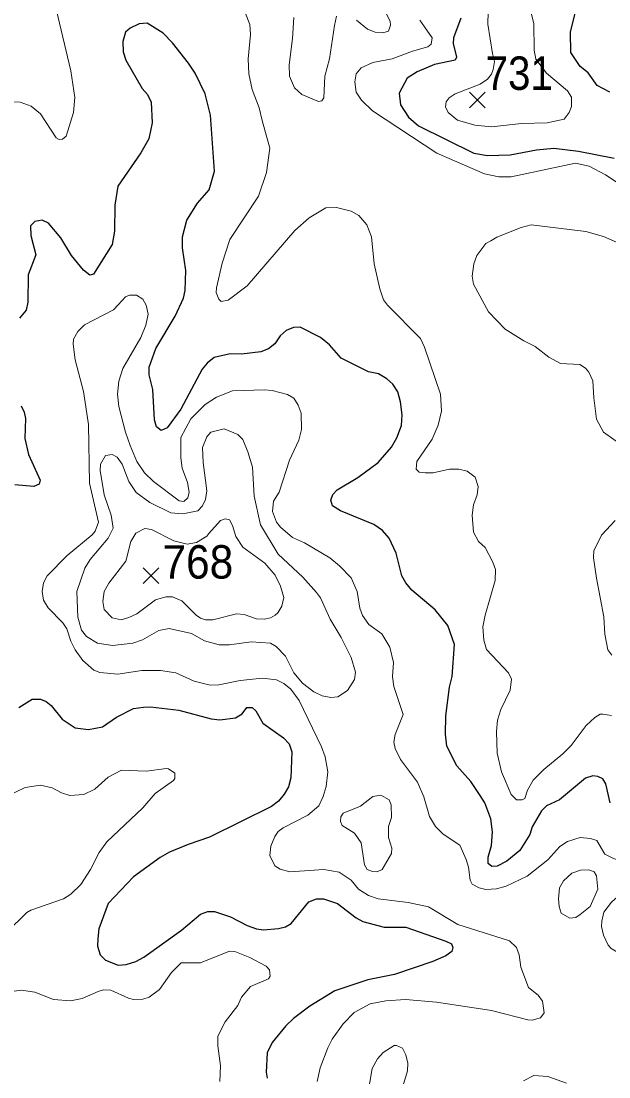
# Model space of a CAD drawing. Extents: x 294.2 to 320.3, y 7482.7 to 7510.7.
# Drawn here: x 317.439 to 318.846, y 7505.662 to 7508.188 of the extents above; entities that cross this region are included whole.
import ezdxf
from ezdxf.enums import TextEntityAlignment as Align

# ---------------------------------------------------------------- set-up
doc = ezdxf.new("R2010")
doc.units = 0
doc.header["$LTSCALE"] = 0.032
for name, color, linetype, lineweight in [('1', 7, 'Continuous', 25), ('2', 7, 'Continuous', 13), ('21', 7, 'Continuous', 25)]:
    doc.layers.add(name, color=color, linetype=linetype, lineweight=lineweight)
doc.layers.add('61', color=7, linetype='Continuous')

msp = doc.modelspace()

# ---------------------------------------------------------------- linework, layer by layer
at = {"layer": '1'}
for points in [[(318.8488, 7508.0179), (318.8183, 7508.034), (318.7967, 7508.0641), (318.7778, 7508.0797), (318.7551, 7508.1125), (318.7546, 7508.1614), (318.7662, 7508.2098)], [(318.4919, 7508.1953), (318.4742, 7508.148), (318.4737, 7508.134), (318.482, 7508.1017), (318.4787, 7508.0942), (318.4293, 7508.084), (318.3875, 7508.0667), (318.3638, 7508.0514), (318.3447, 7508.0156), (318.3472, 7507.9875), (318.3664, 7507.9581), (318.3906, 7507.937), (318.5228, 7507.8719), (318.556, 7507.8662), (318.6103, 7507.8676), (318.6729, 7507.8799), (318.7145, 7507.8843), (318.7733, 7507.8768), (318.8587, 7507.8601)], [(318.0595, 7507.4345), (318.0467, 7507.4156), (318.0312, 7507.4038), (318.0129, 7507.3962), (317.9668, 7507.3909), (317.9402, 7507.3914), (317.9019, 7507.3828), (317.8847, 7507.3693), (317.8731, 7507.3554), (317.8215, 7507.2591), (317.7887, 7507.215), (317.7749, 7507.2085), (317.7632, 7507.2171), (317.7588, 7507.2338), (317.7544, 7507.3064), (317.7461, 7507.3414), (317.7461, 7507.3602), (317.7622, 7507.4043), (317.8082, 7507.4817), (317.8282, 7507.5253), (317.832, 7507.543), (317.8337, 7507.5909), (317.826, 7507.6452), (317.826, 7507.6716), (317.8359, 7507.7119), (317.862, 7507.7522), (317.8897, 7507.7845), (317.9024, 7507.8286), (317.893, 7507.963), (317.8802, 7508.0141), (317.8558, 7508.0636), (317.8398, 7508.0873), (317.802, 7508.1362), (317.7793, 7508.1588), (317.741, 7508.183), (317.7216, 7508.1814), (317.7005, 7508.1712), (317.6889, 7508.1615), (317.6828, 7508.1394), (317.6833, 7508.1141), (317.69, 7508.0948), (317.7294, 7508.027), (317.7416, 7508.0125), (317.7504, 7507.9937), (317.7527, 7507.9448), (317.7449, 7507.9066), (317.7256, 7507.8727), (317.6712, 7507.7931), (317.6634, 7507.7474), (317.6629, 7507.6855), (317.6573, 7507.6532), (317.6129, 7507.5823), (317.604, 7507.5801), (317.5891, 7507.592), (317.5602, 7507.6269), (317.5341, 7507.6694), (317.5047, 7507.7044), (317.4898, 7507.7114), (317.4726, 7507.7087), (317.462, 7507.6979), (317.4626, 7507.6748), (317.4748, 7507.6286), (317.4559, 7507.5807), (317.4553, 7507.5157), (317.4514, 7507.4963), (317.4359, 7507.4775)], [(318.2059, 7507.3812), (318.1776, 7507.4135), (318.156, 7507.4312), (318.1077, 7507.4554), (318.0917, 7507.4549), (318.0739, 7507.4474), (318.0595, 7507.4345)], [(318.8498, 7506.3175), (318.8393, 7506.3632), (318.8321, 7506.3745), (318.8199, 7506.3804), (318.8077, 7506.382), (318.7905, 7506.3761), (318.7278, 7506.3245), (318.6967, 7506.31), (318.6851, 7506.2982), (318.6629, 7506.26), (318.6574, 7506.2417), (318.6329, 7506.2035), (318.6018, 7506.1777), (318.5786, 7506.1659), (318.5658, 7506.1648), (318.5575, 7506.1723), (318.5575, 7506.1874), (318.5652, 7506.2153), (318.568, 7506.2476), (318.5636, 7506.2788), (318.5491, 7506.317), (318.5386, 7506.3347), (318.5159, 7506.368), (318.4821, 7506.4062), (318.4588, 7506.453), (318.4549, 7506.482), (318.456, 7506.5256), (318.4649, 7506.5944), (318.471, 7506.6197), (318.4771, 7506.6961), (318.4605, 7506.7417), (318.4305, 7506.7788), (318.3745, 7506.8261), (318.3606, 7506.8434), (318.3506, 7506.8606), (318.3368, 7506.9144), (318.3201, 7506.9509), (318.3046, 7506.9687), (318.2841, 7506.9832), (318.2037, 7507.016), (318.1848, 7507.0284), (318.1804, 7507.0413), (318.1859, 7507.0553), (318.1959, 7507.066), (318.2458, 7507.0957), (318.2941, 7507.1317), (318.3257, 7507.1688), (318.3385, 7507.1909), (318.3501, 7507.2204), (318.3518, 7507.2457), (318.3479, 7507.2769), (318.3412, 7507.3011), (318.329, 7507.3189), (318.3152, 7507.3323), (318.2952, 7507.3436), (318.2708, 7507.3484), (318.2059, 7507.3812)], [(317.4393, 7507.2673), (317.447, 7507.252), (317.4502, 7507.2367), (317.4479, 7507.1893), (317.4567, 7507.1511), (317.485, 7507.0893), (317.4828, 7507.0796), (317.47, 7507.0742), (317.4245, 7507.0785)], [(317.4343, 7506.5452), (317.4659, 7506.5657), (317.4859, 7506.5657), (317.4997, 7506.5598), (317.5114, 7506.5506), (317.538, 7506.5178), (317.5685, 7506.4968), (317.6007, 7506.4925), (317.6345, 7506.4995), (317.6678, 7506.5221), (317.7083, 7506.5431), (317.7327, 7506.5464), (317.7488, 7506.5474), (317.817, 7506.5388), (317.894, 7506.5184), (317.9151, 7506.5162), (317.9528, 7506.5205), (317.9689, 7506.5302), (317.98, 7506.5453), (317.9927, 7506.5453), (318.0011, 7506.5377), (318.0182, 7506.5081), (318.0671, 7506.4732), (318.081, 7506.4587), (318.0876, 7506.4394), (318.0854, 7506.3775), (318.0798, 7506.356), (318.0687, 7506.3383), (318.0554, 7506.3216), (318.0388, 7506.3082), (317.8907, 7506.235), (317.8391, 7506.2178), (317.7947, 7506.199), (317.7726, 7506.1867)], [(317.7726, 7506.1867), (317.7082, 7506.1404), (317.6478, 7506.0765), (317.6256, 7506.0157), (317.6228, 7505.9926), (317.6222, 7505.9743), (317.6289, 7505.9538)], [(317.6289, 7505.9538), (317.6411, 7505.9409), (317.6716, 7505.9291), (317.691, 7505.9308), (317.7137, 7505.9377), (317.7332, 7505.948), (317.823, 7506.0125), (317.8684, 7506.0507), (317.8862, 7506.0572), (317.9022, 7506.0572), (317.9405, 7506.0448), (317.9804, 7506.0239), (318.0032, 7506.0158), (318.0198, 7506.0131), (318.0558, 7506.0163), (318.0719, 7506.0206), (318.0858, 7506.0287), (318.1279, 7506.0808), (318.1462, 7506.0873), (318.1634, 7506.0878), (318.1967, 7506.0765), (318.2416, 7506.042), (318.2577, 7506.0334), (318.3083, 7506.0197), (318.3607, 7506.0197), (318.4558, 7505.9865), (318.4697, 7505.9801), (318.473, 7505.9715), (318.4708, 7505.9618), (318.4564, 7505.9516), (318.4248, 7505.9376), (318.3333, 7505.9064), (318.269, 7505.894), (318.1902, 7505.8671), (318.1303, 7505.8306), (318.0915, 7505.801), (318.0732, 7505.7838), (318.0405, 7505.7435), (318.0283, 7505.7193), (318.0261, 7505.6725), (318.0283, 7505.6585)]]:
    msp.add_lwpolyline(points, dxfattribs=at)
at = {"layer": '2'}
for points in [[(318.5797, 7506.5152), (318.5879, 7506.5407), (318.6103, 7506.5867), (318.6129, 7506.6135), (318.6058, 7506.6288), (318.5536, 7506.6845), (318.5467, 7506.7062), (318.545, 7506.7385), (318.5501, 7506.7661), (318.5742, 7506.849), (318.5748, 7506.8754), (318.5685, 7506.8933), (318.5501, 7506.9283), (318.534, 7506.9428), (318.5225, 7506.9648), (318.5191, 7507.006), (318.5219, 7507.0305), (318.5311, 7507.0542), (318.5334, 7507.0742), (318.5259, 7507.097), (318.507, 7507.1109), (318.4875, 7507.1159), (318.4651, 7507.1159), (318.4258, 7507.107), (318.4066, 7507.107), (318.3919, 7507.1089), (318.3849, 7507.116), (318.3868, 7507.1345), (318.4232, 7507.1875), (318.4379, 7507.2207), (318.4456, 7507.2545), (318.4436, 7507.2954), (318.4047, 7507.4078), (318.3951, 7507.4282), (318.3164, 7507.5081), (318.3072, 7507.5209), (318.298, 7507.5476), (318.2843, 7507.6075), (318.2779, 7507.6715), (318.2671, 7507.7002), (318.2475, 7507.7225), (318.2292, 7507.733), (318.1947, 7507.7419), (318.1689, 7507.7408), (318.1293, 7507.7171), (318.0943, 7507.6865), (317.9801, 7507.5548), (317.9347, 7507.52), (317.9181, 7507.5167), (317.9124, 7507.5222), (317.906, 7507.5389), (317.9072, 7507.5501), (317.9204, 7507.6091), (317.9387, 7507.6656), (318.0076, 7507.7692), (318.0267, 7507.8253), (318.035, 7507.8841), (318.0165, 7507.9498), (318.0089, 7507.9805), (317.9923, 7508.0245), (317.9846, 7508.0616), (317.9826, 7508.0973), (317.9884, 7508.1561), (317.9865, 7508.1797), (317.9642, 7508.2365)], [(318.5585, 7508.2404), (318.5567, 7508.1803), (318.5681, 7508.1101), (318.5727, 7508.0912), (318.5693, 7508.0723), (318.5654, 7508.0613), (318.556, 7508.0494), (318.5382, 7508.0373), (318.4781, 7508.0143), (318.4641, 7508.0047), (318.457, 7507.9951), (318.4551, 7507.983), (318.4615, 7507.9696), (318.4839, 7507.9511), (318.5254, 7507.9389), (318.565, 7507.9351), (318.6373, 7507.943), (318.699, 7507.9447), (318.7393, 7507.9536), (318.7514, 7507.969), (318.7572, 7507.9837), (318.7565, 7508.006), (318.7476, 7508.0213), (318.6971, 7508.0634), (318.6719, 7508.0972), (318.6677, 7508.1184), (318.6669, 7508.1821), (318.6607, 7508.2073)], [(317.5204, 7508.2301), (317.5587, 7508.0692), (317.5676, 7508.0054), (317.5645, 7507.9696), (317.5472, 7507.9128), (317.5383, 7507.9051), (317.5306, 7507.9045), (317.5236, 7507.9083), (317.4859, 7507.9664), (317.4636, 7507.9843), (317.4374, 7507.9939), (317.4144, 7507.9951), (317.3966, 7507.9939), (317.3736, 7507.9869)], [(318.3028, 7508.2262), (318.3229, 7508.1878), (318.324, 7508.1783), (318.3188, 7508.1639), (318.3051, 7508.16), (318.2873, 7508.1616), (318.2683, 7508.1689), (318.2419, 7508.19)], [(318.194, 7508.2001), (318.1895, 7508.1778), (318.1774, 7508.0973), (318.1665, 7508.0565), (318.164, 7508.0041), (318.1589, 7507.9971), (318.1512, 7507.9958), (318.1114, 7508.0125), (318.0942, 7508.0281), (318.0821, 7508.0559), (318.081, 7508.0832), (318.0893, 7508.1465), (318.0919, 7508.1969)], [(318.3938, 7508.1905), (318.4053, 7508.1739), (318.4232, 7508.1478), (318.4213, 7508.1331), (318.413, 7508.1261), (318.376, 7508.1158), (318.3275, 7508.0973), (318.2815, 7508.089), (318.2537, 7508.076), (318.2411, 7508.0621), (318.2382, 7508.0426), (318.2416, 7508.0181), (318.2543, 7507.9986), (318.2802, 7507.9734), (318.4347, 7507.8719), (318.5484, 7507.8221), (318.5829, 7507.8151), (318.6122, 7507.8151), (318.7667, 7507.8482), (318.7989, 7507.841), (318.8385, 7507.8199), (318.911, 7507.7723)], [(318.8331, 7507.6727), (318.791, 7507.6842), (318.6607, 7507.7008), (318.6365, 7507.6944), (318.5784, 7507.6708), (318.5637, 7507.6619), (318.5522, 7507.6555)], [(318.5522, 7507.6555), (318.5305, 7507.6274), (318.5228, 7507.607), (318.519, 7507.5776), (318.5222, 7507.5585), (318.5579, 7507.4921), (318.5982, 7507.4505), (318.6429, 7507.4225), (318.6697, 7507.4097), (318.7029, 7507.3835), (318.7303, 7507.3688), (318.777, 7507.3663), (318.7903, 7507.3573), (318.7986, 7507.3477), (318.8082, 7507.3273), (318.8101, 7507.2865), (318.817, 7507.2356), (318.8331, 7507.2044), (318.8829, 7507.1689)], [(318.9225, 7507.6332), (318.8331, 7507.6727)], [(318.8369, 7506.1946), (318.8172, 7506.2272), (318.8025, 7506.2323), (318.7776, 7506.2342), (318.7476, 7506.2247), (318.7291, 7506.2132), (318.7003, 7506.1812), (318.6505, 7506.1417), (318.6007, 7506.118), (318.5777, 7506.1116), (318.5522, 7506.1097), (318.5356, 7506.1136), (318.519, 7506.1225), (318.5145, 7506.1321), (318.5107, 7506.1633), (318.5049, 7506.1819), (318.4896, 7506.2157), (318.4494, 7506.2425), (318.4315, 7506.2604), (318.4168, 7506.2847), (318.4034, 7506.3313), (318.3881, 7506.3671), (318.3479, 7506.4207), (318.3351, 7506.4475), (318.3319, 7506.4628), (318.3351, 7506.4807), (318.3536, 7506.5286), (318.3312, 7506.5956), (318.3287, 7506.6186), (318.3306, 7506.6531), (318.3223, 7506.6901), (318.3025, 7506.7214), (318.2719, 7506.7437), (318.2566, 7506.7655), (318.2502, 7506.7833), (318.2438, 7506.8229), (318.2291, 7506.8561), (318.2017, 7506.8848), (318.1787, 7506.9033), (318.1174, 7506.9398), (318.0893, 7506.9525), (318.0606, 7506.9768), (318.051, 7506.989), (318.0412, 7507.0146), (318.0435, 7507.0391), (318.0573, 7507.0608), (318.0816, 7507.1371), (318.104, 7507.1855), (318.1103, 7507.2111), (318.1097, 7507.2494), (318.1027, 7507.2692), (318.0923, 7507.286), (318.0768, 7507.2944), (318.0406, 7507.3039), (318.0223, 7507.3056), (317.9457, 7507.303), (317.9073, 7507.2884), (317.8799, 7507.2705), (317.8454, 7507.2366), (317.8217, 7507.1919), (317.8217, 7507.143), (317.8252, 7507.1185), (317.8377, 7507.084), (317.8416, 7507.0604), (317.8382, 7507.0468), (317.8288, 7507.0387), (317.818, 7507.04), (317.756, 7507.086), (317.7349, 7507.107), (317.7164, 7507.1345), (317.7004, 7507.1728), (317.6889, 7507.2047), (317.6736, 7507.266), (317.6705, 7507.2954), (317.673, 7507.3261), (317.6826, 7507.3567), (317.726, 7507.4308), (317.7381, 7507.4601), (317.7433, 7507.4869), (317.7387, 7507.5086), (317.7305, 7507.5227), (317.7158, 7507.5323), (317.6992, 7507.5323), (317.6896, 7507.5284), (317.6717, 7507.5087), (317.6602, 7507.4971), (317.5913, 7507.4614), (317.5753, 7507.4454), (317.5651, 7507.4269), (317.5638, 7507.4148), (317.5689, 7507.3771), (317.5887, 7507.3018), (317.6008, 7507.2226), (317.6034, 7507.0822), (317.6248, 7506.9889)], [(317.6248, 7506.9889), (317.6168, 7506.9678), (317.6093, 7506.9589), (317.5497, 7506.9095), (317.5014, 7506.8603), (317.4927, 7506.8441), (317.4898, 7506.8229)], [(318.8612, 7506.9927), (318.8293, 7506.9589), (318.8101, 7506.9212), (318.8095, 7506.9034), (318.8165, 7506.8549), (318.8344, 7506.7623), (318.8363, 7506.7208), (318.844, 7506.6831), (318.8535, 7506.6709)], [(317.4898, 7506.8229), (317.493, 7506.8025), (317.5038, 7506.784), (317.5396, 7506.7482), (317.5485, 7506.7335), (317.5581, 7506.7042), (317.5689, 7506.6837), (317.5874, 7506.6582), (317.6136, 7506.6352), (317.6277, 7506.6295), (317.6711, 7506.6256), (317.7286, 7506.6339), (317.7733, 7506.6339), (317.8096, 7506.6282), (317.8537, 7506.6084), (317.892, 7506.5988), (317.9125, 7506.5994), (317.9635, 7506.6103), (318.0172, 7506.616), (318.0504, 7506.6116), (318.0682, 7506.6027), (318.0848, 7506.5892), (318.1046, 7506.5624), (318.1583, 7506.4513), (318.1672, 7506.4271), (318.1736, 7506.3913), (318.1698, 7506.3568), (318.1627, 7506.3326), (318.1519, 7506.3102), (318.1257, 7506.2879), (318.067, 7506.2579), (318.0548, 7506.2489), (318.0465, 7506.2368), (318.0369, 7506.2138), (318.0344, 7506.1915), (318.0471, 7506.1666), (318.0593, 7506.1583), (318.0823, 7506.1519), (318.164, 7506.1576), (318.201, 7506.1512), (318.2291, 7506.1321), (318.247, 7506.1104), (318.2713, 7506.0957), (318.2943, 7506.088), (318.3658, 7506.0791), (318.4143, 7506.0682), (318.4851, 7506.0261), (318.6084, 7505.9872), (318.6256, 7505.9712), (318.632, 7505.9533), (318.6358, 7505.924), (318.6543, 7505.8754), (318.6769, 7505.8574), (318.6872, 7505.8424), (318.6912, 7505.8145), (318.6825, 7505.8026), (318.663, 7505.7976), (318.6527, 7505.7981), (318.565, 7505.8205), (318.4335, 7505.8403), (318.3594, 7505.8467), (318.3121, 7505.8435), (318.2751, 7505.8365), (318.2368, 7505.8154), (318.2106, 7505.7886), (318.1838, 7505.7515), (318.1736, 7505.7311), (318.155, 7505.6832), (318.148, 7505.6507)], [(318.8529, 7506.526), (318.8317, 7506.5299), (318.8254, 7506.5294), (318.8127, 7506.5216), (318.7921, 7506.5027), (318.7559, 7506.4545), (318.7361, 7506.4347), (318.6907, 7506.3971), (318.6652, 7506.3715), (318.6518, 7506.3479), (318.6448, 7506.3281), (318.639, 7506.3249)], [(318.639, 7506.3249), (318.6256, 7506.3243), (318.6122, 7506.337), (318.5892, 7506.3913), (318.579, 7506.436), (318.5771, 7506.4884), (318.5797, 7506.5152)], [(317.3806, 7506.3217), (317.4489, 7506.3543), (317.486, 7506.3594), (317.514, 7506.3536), (317.5364, 7506.3409), (317.5562, 7506.3351), (317.5894, 7506.337), (317.6155, 7506.3498), (317.6481, 7506.3785), (317.68, 7506.3958), (317.7388, 7506.3932), (317.7873, 7506.3996), (317.7924, 7506.399), (317.8071, 7506.3881), (317.8077, 7506.3753), (317.8039, 7506.3709), (317.7605, 7506.3396), (317.7311, 7506.3057), (317.6449, 7506.224), (317.6264, 7506.1985), (317.6053, 7506.1576), (317.5824, 7506.1219), (317.5587, 7506.0989), (317.5409, 7506.088), (317.463, 7506.0606), (317.4534, 7506.0548), (317.4049, 7506.0082)], [(318.897, 7506.1199), (318.9033, 7506.1334), (318.9053, 7506.1513), (318.904, 7506.1615), (318.897, 7506.171), (318.8574, 7506.1838), (318.8369, 7506.1946)], [(319.2364, 7505.6612), (319.2065, 7505.6717), (319.1473, 7505.6749), (319.1294, 7505.68), (319.1191, 7505.6877), (319.1115, 7505.7062), (319.0981, 7505.7222), (319.0176, 7505.7566), (318.9959, 7505.7727), (318.9758, 7505.8105), (318.9653, 7505.8499), (318.948, 7505.8908), (318.9314, 7505.9144), (318.9078, 7505.9361), (318.8516, 7505.9686), (318.8446, 7505.9769), (318.8331, 7506.0006), (318.8287, 7506.0216), (318.8299, 7506.0338), (318.8344, 7506.0554), (318.8523, 7506.0797), (318.897, 7506.1199)], [(317.3812, 7505.8614), (317.44, 7505.869), (317.4719, 7505.8645), (317.5166, 7505.8467), (317.5575, 7505.8435), (317.5856, 7505.8492), (317.6239, 7505.8658), (317.6366, 7505.8697), (317.6538, 7505.869), (317.6966, 7505.8499), (317.7081, 7505.8467), (317.7311, 7505.8473), (317.7458, 7505.8524), (317.7707, 7505.8703), (317.7994, 7505.9112), (317.8224, 7505.9341), (317.869, 7505.9341), (317.938, 7505.9622)], [(317.938, 7505.9622), (317.9508, 7505.9616), (317.9865, 7505.9476), (318.0261, 7505.9265), (318.0337, 7505.9175), (318.0357, 7505.9028), (318.0312, 7505.8965)], [(318.0312, 7505.8965), (317.9884, 7505.878), (317.9673, 7505.8524), (317.9578, 7505.832), (317.9277, 7505.7931), (317.9099, 7505.7592), (317.9099, 7505.7362), (317.9163, 7505.6877), (317.915, 7505.6507)], [(318.6422, 7505.652), (318.6671, 7505.6647), (318.7003, 7505.6628), (318.745, 7505.6462)]]:
    msp.add_lwpolyline(points, dxfattribs=at)
for points in [[(318.2208, 7506.5864), (318.1978, 7506.5713), (318.1806, 7506.5694), (318.1602, 7506.5733), (318.1404, 7506.5828), (318.1129, 7506.6039), (318.0925, 7506.6288), (318.072, 7506.6684), (318.0497, 7506.6914), (318.0363, 7506.6997), (317.9903, 7506.7029), (317.938, 7506.6952), (317.9137, 7506.6952), (317.8786, 7506.7048), (317.8473, 7506.7227), (317.7937, 7506.7348), (317.7694, 7506.7297), (317.7299, 7506.7074), (317.7069, 7506.6997), (317.6583, 7506.6939), (317.6226, 7506.6997), (317.5958, 7506.7156), (317.5836, 7506.7303), (317.5753, 7506.7616), (317.5727, 7506.8229), (317.5919, 7506.8791), (317.6047, 7506.8995), (317.6476, 7506.9503), (317.6594, 7506.9747), (317.6547, 7507.0061), (317.6385, 7507.0547), (317.6283, 7507.1128), (317.6296, 7507.1281), (317.6417, 7507.1485), (317.6571, 7507.1505), (317.6692, 7507.1447), (317.6813, 7507.1274), (317.6973, 7507.086), (317.7151, 7507.0601), (317.7472, 7507.0357), (317.7976, 7507.0115), (317.8268, 7507.0089), (317.8626, 7507.016), (317.8736, 7507.0278), (317.8807, 7507.0435), (317.8838, 7507.0639), (317.8748, 7507.132), (317.8735, 7507.1677), (317.8843, 7507.1932), (317.8939, 7507.2047), (317.9258, 7507.2124), (317.9584, 7507.199), (317.9699, 7507.1868), (317.982, 7507.1575), (317.9929, 7507.1205), (317.9974, 7507.0508), (318.0122, 7506.9826), (318.0547, 7506.9126), (318.1136, 7506.8571), (318.1461, 7506.821), (318.1557, 7506.8076), (318.1793, 7506.7565), (318.2055, 7506.7131), (318.2291, 7506.6652), (318.24, 7506.6301), (318.2374, 7506.6122)], [(318.0637, 7506.7877), (318.0542, 7506.7718), (318.0472, 7506.7661), (318.0363, 7506.7597), (318.021, 7506.7565), (318.0031, 7506.7578), (317.9737, 7506.768), (317.9546, 7506.7693), (317.8984, 7506.7552), (317.8805, 7506.7552), (317.8684, 7506.7591), (317.8588, 7506.7667), (317.8243, 7506.8006), (317.802, 7506.8101), (317.786, 7506.8101), (317.7611, 7506.8031), (317.7164, 7506.7694), (317.6975, 7506.7608), (317.6786, 7506.7553), (317.6574, 7506.76), (317.6383, 7506.78), (317.6349, 7506.7995), (317.6378, 7506.8227), (317.6492, 7506.8426), (317.6902, 7506.8957), (317.7024, 7506.943), (317.7139, 7506.9627), (317.7356, 7506.9736), (317.7516, 7506.9717), (317.8052, 7506.9442), (317.8371, 7506.9365), (317.8592, 7506.9404), (317.8837, 7506.9557), (317.8888, 7506.9621), (317.9163, 7506.9927), (317.9278, 7506.9972), (317.938, 7506.9947), (317.9456, 7506.9806), (317.9533, 7506.9545), (317.9705, 7506.9289), (318.0229, 7506.8912), (318.0478, 7506.8625), (318.0605, 7506.8357), (318.0682, 7506.8089)], [(318.3185, 7506.2611), (318.3192, 7506.2343), (318.3268, 7506.2087), (318.3261, 7506.1959), (318.3038, 7506.1576), (318.2917, 7506.1519), (318.2802, 7506.1532), (318.2674, 7506.1582), (318.2617, 7506.1691), (318.2534, 7506.2214), (318.2374, 7506.2444), (318.2081, 7506.263), (318.2042, 7506.2726), (318.2048, 7506.2841), (318.2106, 7506.2924), (318.2521, 7506.309), (318.2815, 7506.3325), (318.3006, 7506.3358), (318.3204, 7506.3243), (318.3249, 7506.3122), (318.3261, 7506.2821)], [(318.7775, 7506.05), (318.7673, 7506.0433), (318.7527, 7506.0414), (318.7322, 7506.0535), (318.7271, 7506.0695), (318.7258, 7506.0874), (318.7284, 7506.1142), (318.738, 7506.1308), (318.7578, 7506.1493), (318.7782, 7506.1563), (318.7987, 7506.157), (318.8108, 7506.1525), (318.8165, 7506.1429), (318.8197, 7506.1104), (318.8012, 7506.0695)], [(318.3089, 7505.5414), (318.3013, 7505.4962), (318.2789, 7505.4623), (318.2649, 7505.4521), (318.2515, 7505.4514), (318.2387, 7505.4604), (318.2349, 7505.4847), (318.2368, 7505.5051), (318.2636, 7505.5881), (318.2796, 7505.6813), (318.2923, 7505.7049), (318.3057, 7505.7196), (318.3326, 7505.7369), (318.3377, 7505.7369), (318.3523, 7505.7299), (318.3606, 7505.7145), (318.3651, 7505.6941), (318.3645, 7505.6762), (318.3555, 7505.6469), (318.3153, 7505.5702)]]:
    msp.add_lwpolyline(points, close=True, dxfattribs=at)
at = {"layer": '21'}
for p, q in [((318.5124, 7508.0178), (318.5499, 7507.9803)), ((318.5499, 7508.0178), (318.5124, 7507.9803)), ((317.7317, 7506.8793), (317.7692, 7506.8418)), ((317.7692, 7506.8793), (317.7317, 7506.8418))]:
    msp.add_line(p, q, dxfattribs=at)

# ---------------------------------------------------------------- texts
at = {"layer": '61'}
for s, width, p in [('731', 0.9, (318.6318, 7508.0234)), ('768', 0.95, (317.8624, 7506.8539))]:
    msp.add_text(s, height=0.08, dxfattribs=dict(at, width=width)).set_placement(p, align=Align.CENTER)

doc.saveas('drawing.dxf')
